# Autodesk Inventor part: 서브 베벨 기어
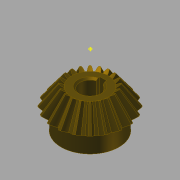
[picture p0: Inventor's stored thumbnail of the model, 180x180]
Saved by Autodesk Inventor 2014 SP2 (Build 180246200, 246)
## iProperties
Created: 2014-10
Part Number: 서브 베벨 기어
Material: 강철, 탄소
Document SubType Name: Modeling
Designer: KYOUNG IL JANG
Categories: <?xml version="1.0" encoding="UTF-16"?> <MemberInstance><Categories><FamilyTemplate><FamilyTemplateParameter ValueType="xs:double" Id="1" ObjectReferenceKey="da
Mass: 135.037 g
Surface Area: 63.6518 cm^2
Volume: 17.1585 cm^3
Density: 7.87 g/cm^3
Appearance: 얼룩무늬
CustomPartVersion: 1
Author: SeoGD™ [www.esajin.kr]
Revision Number: 1
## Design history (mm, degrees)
node "맨 위 점"
node "메쉬 평면2"
sketch "톱니 본체 스케치"
  geometry: L1 (0, 0)-(18.003, -31.331); L2 (18.003, -31.331)-(21.664, -28.891); L3 (21.664, -28.891)-(0, 0); L4 (20, -30)-(0, 0); L5 (10.813, -18.818)-(13.012, -17.352); L6 (18.003, -31.331)-(10.813, -18.818); L7 (21.664, -28.891)-(13.012, -17.352); L8 (0, -39.387)-(0, 6.564) reference; L9 (0, -30)-(21.664, -30)
  constraints: 16 end point, 4 point on line, 3 perpendicular, 2 collinear, 1 horizontal alignment, 1 vertical alignment
  dimensions: "d0" = 40 diameter of L4.start L8 (= da_de); "d1" = 36.00616 diameter of L1.end L8 (= da_dfe); "d2" = 43.3282 diameter of L2.end L8 (= da_dae); "d3" = 14.4 distance between parallel lines of L2 L5 (= da_b); "d4" = 28.8906 vertical distance of L2.end L1.start (= da_ve)
revolve "톱니 본체" sketch "톱니 본체 스케치" stored, may be unused: angle "d5" = 90 deg
node "시작점"
node "톱니 평면"
sketch "시작 스케치"
  geometry: L1 (0, -23.505)-(0, 10.645) reference; L2 (-0.834, -2.928)-(0.834, -2.928); A1 r 8.898 centre (-9.698, -3.713) between (-0.834, -2.928) and (-3.903, 3.04); A2 r 8.898 centre (9.698, -3.713) between (3.903, 3.04) and (0.834, -2.928); A3 r 27.357 centre (0, -24.037) between (3.903, 3.04) and (-3.903, 3.04); 1 further point
  constraints: 6 point on circle, 3 centre point, 3 symmetric about line, 2 end point, 1 coincident, 1 perpendicular, 1 other
  dimensions: "d7" = 8.89846 radius of A1 (= fd_rr); "d8" = 9.69794 horizontal distance of point (0, -24.037) A1.centre (= fd_x); "d9" = 20.32439 vertical distance of point (0, -24.037) A1.centre (= fd_y); "d57" = 27.35701 radius of A3 (= 0.5 x fd_dva + 0.3 x da_he); "d58" = 21.10901 distance from line of A3.centre L2 (= 0.5 x fd_dva - 1.12 x da_he)
node "끝점"
  node "끝 평면"
sketch "3D 스케치 오른쪽"
  node "Helical Curve Right" dims "d65" = 229.90621 (computed from da_dm, da_delta, da_beta), "d66" = 31.5, "d67" = 40 (= da_de), "d68" = -5.88003 (= -da_delta), "d69" = 12.16458 (computed from fd_loft, da_delta)
node "끝 평면 오른쪽"
sketch "끝 스케치 오른쪽"
  geometry: L1 (0, -22.649)-(0, 12.15) reference; L2 (-0.497, -1.72)-(0.497, -1.72); A1 r 5.299 centre (-5.775, -2.187) between (-0.497, -1.72) and (-2.324, 1.834); A2 r 5.299 centre (5.775, -2.187) between (2.324, 1.834) and (0.497, -1.72); A3 r 16.291 centre (0, -14.29) between (2.324, 1.834) and (-2.324, 1.834); 1 further point
  constraints: 6 point on circle, 3 centre point, 3 symmetric about line, 2 end point, 1 coincident, 1 perpendicular, 1 other
  dimensions: "d70" = 5.77526 horizontal distance of A3.centre A1.centre (computed from fd_x, fd_ratio); "d71" = 12.10346 vertical distance of point (0, -14.29) A1.centre (computed from fd_y, fd_ratio); "d72" = 5.29916 radius of A1 (computed from fd_rr, fd_ratio); "d73" = 12.57071 distance from line of point (0, -14.29) L2 (computed from d58, fd_ratio); "d74" = 16.29149 radius of A3 (computed from d57, fd_ratio)
feature "로프트 오른쪽" sketch "끝 스케치 오른쪽" dims "d75" = 0, "d77" = 0, "d79" = 0, "d80" = 90 deg, "d85" = 20, "d92" = 90 deg, "d93" = 90 deg, "da_teethtype" = 0 [user parameter]
sketch "3D 스케치 왼쪽"
  node "Helical Curve Left" dims "d26" = 229.90621 (computed from da_dm, da_delta, da_beta), "d27" = 12.16458 (computed from fd_loft, da_delta), "d28" = 40 (= da_de), "d29" = -5.88003 (= -da_delta)
node "끝 평면 왼쪽"
sketch "끝 스케치 왼쪽" dims "d56" = 10.82768 (derived)
  geometry: L1 (0, -35.087)-(0, 18.089) reference; L2 (-0.497, -1.716)-(0.497, -1.716); A1 r 5.299 centre (-5.775, -2.183) between (-0.497, -1.716) and (-2.324, 1.838); A2 r 5.299 centre (5.775, -2.183) between (2.324, 1.838) and (0.497, -1.716); A3 r 16.291 centre (0, -14.287) between (2.324, 1.838) and (-2.324, 1.838); 2 further points; 1 other entity
  constraints: 6 point on circle, 3 centre point, 3 symmetric about line, 2 end point, 1 coincident, 2 other
  dimensions: "d30" = 5.29916 radius of A1 (computed from fd_rr, fd_ratio); "d31" = 5.77526 horizontal distance of point (0, -14.287) A1.centre (computed from fd_x, fd_ratio); "d32" = 12.10346 vertical distance of A1.centre point (0, -14.287) (computed from fd_y, fd_ratio); "d61" = 16.29149 radius of A3 (computed from d57, fd_ratio); "d62" = 12.57071 distance from line of point (0, -14.287) L2 (computed from d58, fd_ratio)
feature "로프트 왼쪽" sketch "끝 스케치 왼쪽" dims "d35" = 0, "d37" = 0, "d39" = 0, "d40" = 90 deg, "d84" = 10, "d90" = 90 deg, "d91" = 90 deg, "da_teethtype" = 0 [user parameter]
sketch "본체 스케치"
  geometry: L1 (0, -35.038)-(0, -19.531) reference; L2 (18.003, -31.331)-(10.813, -18.818) reference; L3 (10.813, -18.818)-(0, -18.818); L4 (18.003, -31.331)-(0, -31.331)
  constraints: 4 end point, 2 perpendicular, 2 point on line
revolve "본체 고정" sketch "본체 스케치" stored, may be unused: angle "d46" = 90 deg
feature "피치 지름" dims angle "d47" = 90 deg
sketch "스케치8"
  geometry: C1 r 17 at (0, 0); 1 further point
  constraints: 1 centre point, 1 coincident
  dimensions: "d94" = 34 diameter of C1
extrude "돌출1" join sketch "스케치8" distance "d95" = 10; taper "d96" = 0 deg
sketch "스케치9"
  geometry: 1 further point
hole "구멍1" sketch "스케치9" at (0, 0) diameter "d97" = 12; stored, may be unused: countersink angle "d101" = 90 deg, drill point angle "d103" = 118 deg; dims "d98" = 6, "d99" = 4, "d100" = 2, "d102" = 8
sketch "스케치10"
  geometry: 1 further point
sketch "스케치11"
  geometry: 1 further point
sketch "스케치12"
  geometry: L1 (-2, 5.657)-(-2, 7.8); L2 (-2, 7.8)-(2, 7.8); L3 (2, 7.8)-(2, 5.657); A1 r 6 centre (0, 0) between (-2, 5.657) and (2, 5.657) reference; 1 further point
  constraints: 6 end point, 2 parallel, 2 point on circle, 1 perpendicular, 1 vertical
  dimensions: "d104" = 4 distance of L1.end L2.end; "d105" = 13.8 dimension on A1 L2
extrude "돌출2" cut sketch "스케치12" stored distance "d106" = 7; taper "d107" = 0 deg
chamfer "모따기1" distance "d108" = 1; stored, may be unused: second distance "d109" = 2, angle "d110" = 45 deg
body "Solid1"
feature "로프트" dims "d17" = 0, "d18" = 90 deg, "d19" = 0, "d20" = 90 deg, "d89" = 0, "da_teethtype" = 0 [user parameter]
pattern_circular "원형 패턴" dims angle "d22" = 360 deg, "d88" = 0, "da_teethtype" = 0 [user parameter]
pattern_circular "원형 패턴 오른쪽" dims angle "d82" = 360 deg, "da_teethtype" = 0 [user parameter]
pattern_circular "원형 패턴 왼쪽" dims angle "d42" = 360 deg, "da_teethtype" = 0 [user parameter]
sketch "끝 스케치"
  geometry: L1 (0, -15.359)-(0, 6.983) reference; L2 (-0.497, -1.72)-(0.497, -1.72); A1 r 5.299 centre (-5.775, -2.187) between (-0.497, -1.72) and (-2.324, 1.834); A2 r 5.299 centre (5.775, -2.187) between (2.324, 1.834) and (0.497, -1.72); A3 r 16.291 centre (0, -14.29) between (2.324, 1.834) and (-2.324, 1.834); 1 further point
  constraints: 6 point on circle, 3 centre point, 3 symmetric about line, 2 end point, 1 coincident, 1 other
  dimensions: "d12" = 5.29916 radius of A1 (computed from fd_rr, fd_ratio); "d15" = 5.77526 horizontal distance of A1.centre point (0, -14.29) (computed from fd_x, fd_ratio); "d16" = 12.10346 vertical distance of A1.centre point (0, -14.29) (computed from fd_y, fd_ratio); "d59" = 16.29149 radius of A3 (computed from d57, fd_ratio); "d60" = 12.57071 distance from line of A3.centre L2 (computed from d58, fd_ratio)
sketch "Sketch6"
  geometry: L1 (20, -30)-(0, 0) reference; L2 (0, -37.8)-(0, 6.3) reference
body "Srf1"
other parameters: "da_b" = 14.4 [user parameter; used in 2 equation terms], "da_de" = 40 [user parameter; used in 4 equation terms], "da_dae" = 43.3282 [user parameter; used in 2 equation terms], "da_dfe" = 36.00616 [user parameter; used in 1 equation term], "da_le" = 36.05551 [user parameter; used in 1 equation term], "da_omega" = 90 deg [user parameter; used in 1 equation term], "da_beta" = 0 [user parameter; used in 2 equation terms], "da_delta" = 5.88003 [user parameter; used in 8 equation terms], "da_alpha" = 20 deg [user parameter; used in 2 equation terms], "da_he" = 4.4 [user parameter; used in 4 equation terms], "da_ve" = 28.8906 [user parameter; used in 1 equation term], "fd_dv" = 48.07402 (computed from da_de, da_delta) [user parameter; used in 1 equation term], "fd_dva" = 52.07402 (computed from da_dae, da_delta) [user parameter; used in 3 equation terms], "fd_dvb" = 45.1748 (computed from fd_dv, da_alpha) [user parameter; used in 2 equation terms], "da_zv" = 240.37008 [user parameter; used in 1 equation term], "fd_loft" = 14.62 (= da_b + 0.05 x da_he) [user parameter; used in 4 equation terms], "fd_ratio" = 5.95514 (computed from da_le, fd_loft) [user parameter; used in 15 equation terms], "fd_rr" = 8.89846 (computed from fd_dd, fd_dvb) [user parameter; used in 6 equation terms], "fd_angle" = 0.66075 (computed from da_zv) [user parameter; used in 4 equation terms], "fd_x1" = 1.58709 (computed from da_dvw, fd_angle) [user parameter; used in 1 equation term], "fd_y1" = 23.98456 (computed from da_dvw, fd_angle) [user parameter; used in 1 equation term], "fd_x2" = 8.11084 (computed from fd_rr, fd_angle2, fd_angle) [user parameter; used in 1 equation term], "fd_y2" = 3.66016 (computed from fd_rr, fd_angle2, fd_angle) [user parameter; used in 1 equation term], "fd_x" = 9.69794 (= fd_x1 + fd_x2) [user parameter; used in 4 equation terms], "fd_y" = 20.32439 (= fd_y1 - fd_y2) [user parameter; used in 4 equation terms], "fd_angle2" = 3.57832 (computed from fd_dvb, fd_dd, da_alpha) [user parameter; used in 2 equation terms], "fd_dd" = 48.55402 (= fd_dva - 0.8 x da_he) [user parameter; used in 2 equation terms], "da_dvw" = 48.07402 [user parameter; used in 2 equation terms], "d11" = 14.62 (= fd_loft), "da_dm" = 32.01232 [user parameter; used in 2 equation terms], "da_x" = 0 [user parameter], "da_m" = 2 [user parameter], "d48" = 0, "d49" = 0, "d50" = 90 deg (= da_omega), "d51" = 9 deg (computed from da_z), "d52" = 0, "d53" = 0, "d54" = 0
